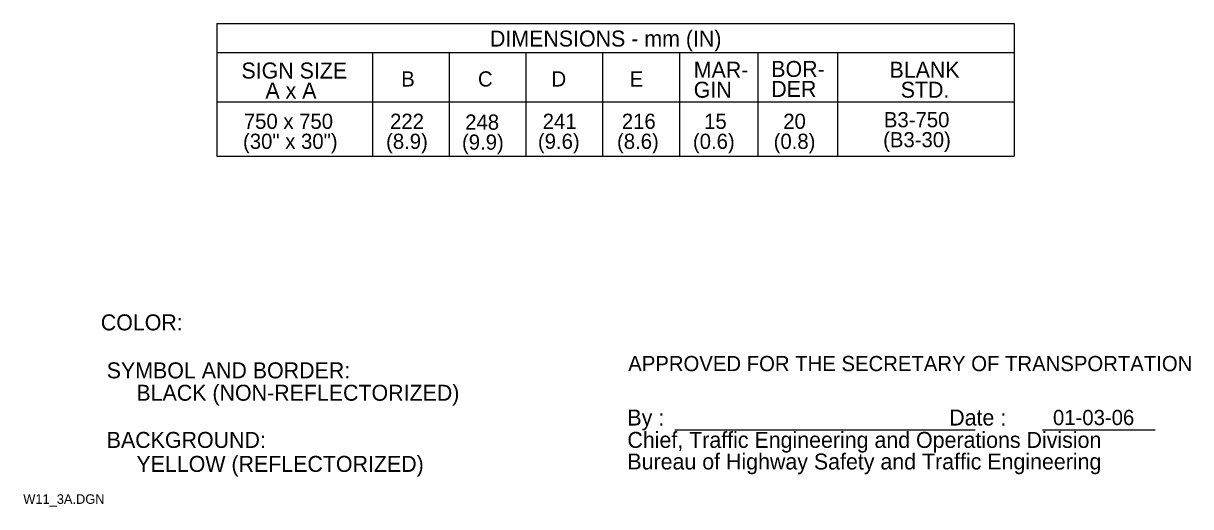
# Model space of a CAD drawing. Extents: x 0.013 to 0.196, y 0.005 to 0.259.
# Drawn here: x 0.013 to 0.1956, y 0.0047 to 0.0803 of the extents above; entities that cross this region are included whole.
import ezdxf

# ---------------------------------------------------------------- set-up
doc = ezdxf.new("R2010")
doc.units = 0
for name, color, linetype in [('1', 7, 'Continuous'), ('3', 7, 'Continuous'), ('4', 7, 'Continuous')]:
    doc.layers.add(name, color=color, linetype=linetype)

msp = doc.modelspace()

# ---------------------------------------------------------------- linework, layer by layer
at = {"layer": '1'}
for p, q in [((0.168, 0.08025), (0.168, 0.059500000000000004)), ((0.12788657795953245, 0.07563878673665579), (0.12788657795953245, 0.059513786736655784)), ((0.14038657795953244, 0.07563878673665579), (0.14038657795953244, 0.059513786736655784)), ((0.11490984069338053, 0.01672517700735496), (0.16191318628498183, 0.01672517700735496)), ((0.17242323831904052, 0.01672517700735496), (0.19003484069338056, 0.01672517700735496))]:
    msp.add_line(p, q, dxfattribs=at)
at = {"layer": '3'}
for p, q in [((0.043250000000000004, 0.08025), (0.168, 0.08025)), ((0.043250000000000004, 0.08025), (0.043250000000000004, 0.059500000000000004)), ((0.168, 0.075625), (0.043250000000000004, 0.075625)), ((0.06763657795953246, 0.07563878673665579), (0.06763657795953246, 0.059513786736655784)), ((0.043250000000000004, 0.068), (0.168, 0.068)), ((0.043250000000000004, 0.059500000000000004), (0.168, 0.059500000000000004))]:
    msp.add_line(p, q, dxfattribs=at)
for points in [[(0.079625, 0.075625), (0.079625, 0.059500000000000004)], [(0.091625, 0.075625), (0.091625, 0.059500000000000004)], [(0.10362500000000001, 0.075625), (0.10362500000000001, 0.059500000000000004)], [(0.11563657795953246, 0.07563878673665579), (0.11563657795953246, 0.059513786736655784)]]:
    msp.add_lwpolyline(points, dxfattribs=at)

# ---------------------------------------------------------------- texts
at = {"layer": '1'}
for s, height, p in [('COLOR:', 0.0024997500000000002, (0.025125, 0.03225)), ('APPROVED FOR THE SECRETARY OF TRANSPORTATION', 0.0023752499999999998, (0.107625, 0.025875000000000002)), (' SYMBOL AND BORDER:', 0.0024997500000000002, (0.025125, 0.02475)), ('      BLACK (NON-REFLECTORIZED)', 0.0024997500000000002, (0.025125, 0.02125)), ('By :                                                Date :', 0.0024997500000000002, (0.1075, 0.017375)), ('Chief, Traffic Engineering and Operations Division', 0.0024997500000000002, (0.1075, 0.013875)), (' BACKGROUND:', 0.0024997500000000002, (0.025125, 0.013875)), ('Bureau of Highway Safety and Traffic Engineering', 0.0024997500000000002, (0.1075, 0.0105)), ('      YELLOW (REFLECTORIZED)', 0.0024997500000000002, (0.025125, 0.010125)), ('W11_3A.DGN', 0.0015, (0.013000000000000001, 0.005125))]:
    msp.add_text(s, height=height, dxfattribs=at).set_placement(p)
at = {"layer": '3'}
for s, height, p in [('DIMENSIONS - mm (IN)', 0.0024997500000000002, (0.08600000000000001, 0.076625)), ('SIGN SIZE', 0.0024997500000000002, (0.047125, 0.07162500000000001)), ('MAR-', 0.0024997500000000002, (0.11787500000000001, 0.07175000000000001)), ('BOR-', 0.0024997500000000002, (0.13, 0.07187500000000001)), ('BLANK', 0.0024997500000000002, (0.1485, 0.07175000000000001)), ('B', 0.0023752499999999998, (0.072125, 0.07037500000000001)), ('C', 0.0023752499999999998, (0.084125, 0.07037500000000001)), ('D', 0.0023752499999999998, (0.095625, 0.07037500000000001)), ('E', 0.0023752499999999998, (0.107875, 0.07037500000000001)), ('DER', 0.0024997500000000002, (0.13, 0.06875)), ('A x A', 0.0024997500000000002, (0.050875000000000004, 0.0685)), ('GIN', 0.0024997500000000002, (0.11787500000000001, 0.068625)), ('STD.', 0.0024997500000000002, (0.15025, 0.068625)), ('750 x 750', 0.0023752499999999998, (0.0475, 0.06375)), ('222', 0.0023752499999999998, (0.07037500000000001, 0.06375)), ('248', 0.0023752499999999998, (0.082125, 0.063625)), ('241', 0.0023752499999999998, (0.09425, 0.06375)), ('216', 0.0023752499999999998, (0.106625, 0.06375)), ('15', 0.0023752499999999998, (0.11950000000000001, 0.06375)), ('20', 0.0023752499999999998, (0.131875, 0.06375)), ('B3-750', 0.0023752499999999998, (0.147625, 0.064)), ('(30" x 30")', 0.0023752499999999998, (0.047375, 0.060625)), ('(8.9)', 0.0023752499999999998, (0.06975, 0.060625)), ('(9.9)', 0.0023752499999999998, (0.081625, 0.0605)), ('(9.6)', 0.0023752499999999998, (0.0935, 0.060625)), ('(8.6)', 0.0023752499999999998, (0.105875, 0.060625)), ('(0.6)', 0.0023752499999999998, (0.11775000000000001, 0.060625)), ('(0.8)', 0.0023752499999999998, (0.130375, 0.060625)), ('(B3-30)', 0.0023752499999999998, (0.1475, 0.060875))]:
    msp.add_text(s, height=height, dxfattribs=at).set_placement(p)
at = {"layer": '4'}
msp.add_text('01-03-06', height=0.0023752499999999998, dxfattribs=at).set_placement((0.17406896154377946, 0.017442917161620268))

doc.saveas('drawing.dxf')
